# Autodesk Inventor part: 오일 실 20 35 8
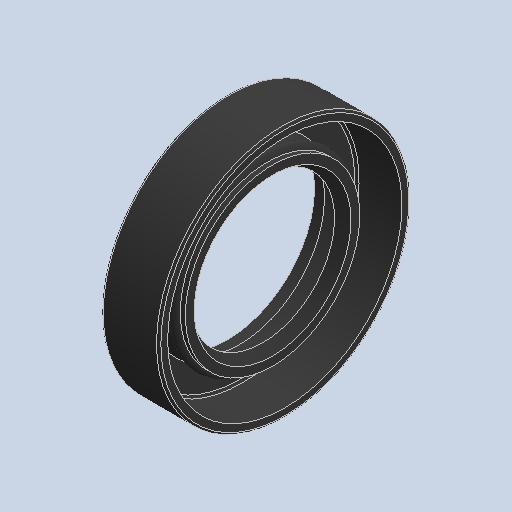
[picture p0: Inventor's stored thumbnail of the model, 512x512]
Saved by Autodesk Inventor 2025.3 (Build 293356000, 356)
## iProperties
Created: 2026-01
Part Number: 오일 실 20 35 8
Material: 고무
Description: 오일-실
Document SubType Name: Modeling
Designer: PC-13
Density: 0.93 g/cm^3
Appearance: 기본값
Author: jhkim
Sending System: Autodesk Inventor 2026
Preprocessor: ST-DEVELOPER v20.1
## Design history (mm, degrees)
feature "Solid1"
node "솔리드1"
